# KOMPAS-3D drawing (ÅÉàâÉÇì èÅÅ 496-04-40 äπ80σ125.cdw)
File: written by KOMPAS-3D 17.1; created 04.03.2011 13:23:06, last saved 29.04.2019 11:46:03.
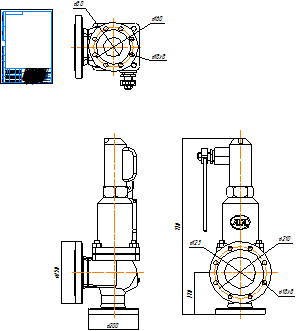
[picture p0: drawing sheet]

Sheet 1: A4, portrait

Title block, sheet 1: name: Прегран Ду 80х125; material: Внимание! Данный продукт является объектом авторского права ООО «Торговый Дом АДЛ». / Запрещается изменение, копирование, распространение / (в том числе путем копирования на другие сайты и ресурсы в Интернете) / или любое иное использование информации и объектов без предварительного / согласия правообладателя (ООО «Торговый Дом АДЛ»).; scale: 1:1; sheets: 1; organisation: ООО "Торговый дом АДЛ"; sheet format: A4; stored path: C:\Users\tra\Desktop\2д чертежи\Предохранительные клапаны ПРЕГРАН\ПРЕГРАН 496\ПРЕГРАН КПП 496-04-40\KOMPAS 2D\Прегран Ду 80х125.cdw

Views: Спереди 1, Проекционный вид 2, Проекционный вид 3
Dimensions and other numbers on the sheet: 200; 250; 170; 710; 210; 18; 125; 160; 80; 1:1; 1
